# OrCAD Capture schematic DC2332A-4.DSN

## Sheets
1 PAGE5 - LTC3769: size Custom; company: ANALOG DEVICES; note: DEMO BOARD BILL OF MATERIALS; note: MULTIPHASE BOOST CONVERTER EXPANDER
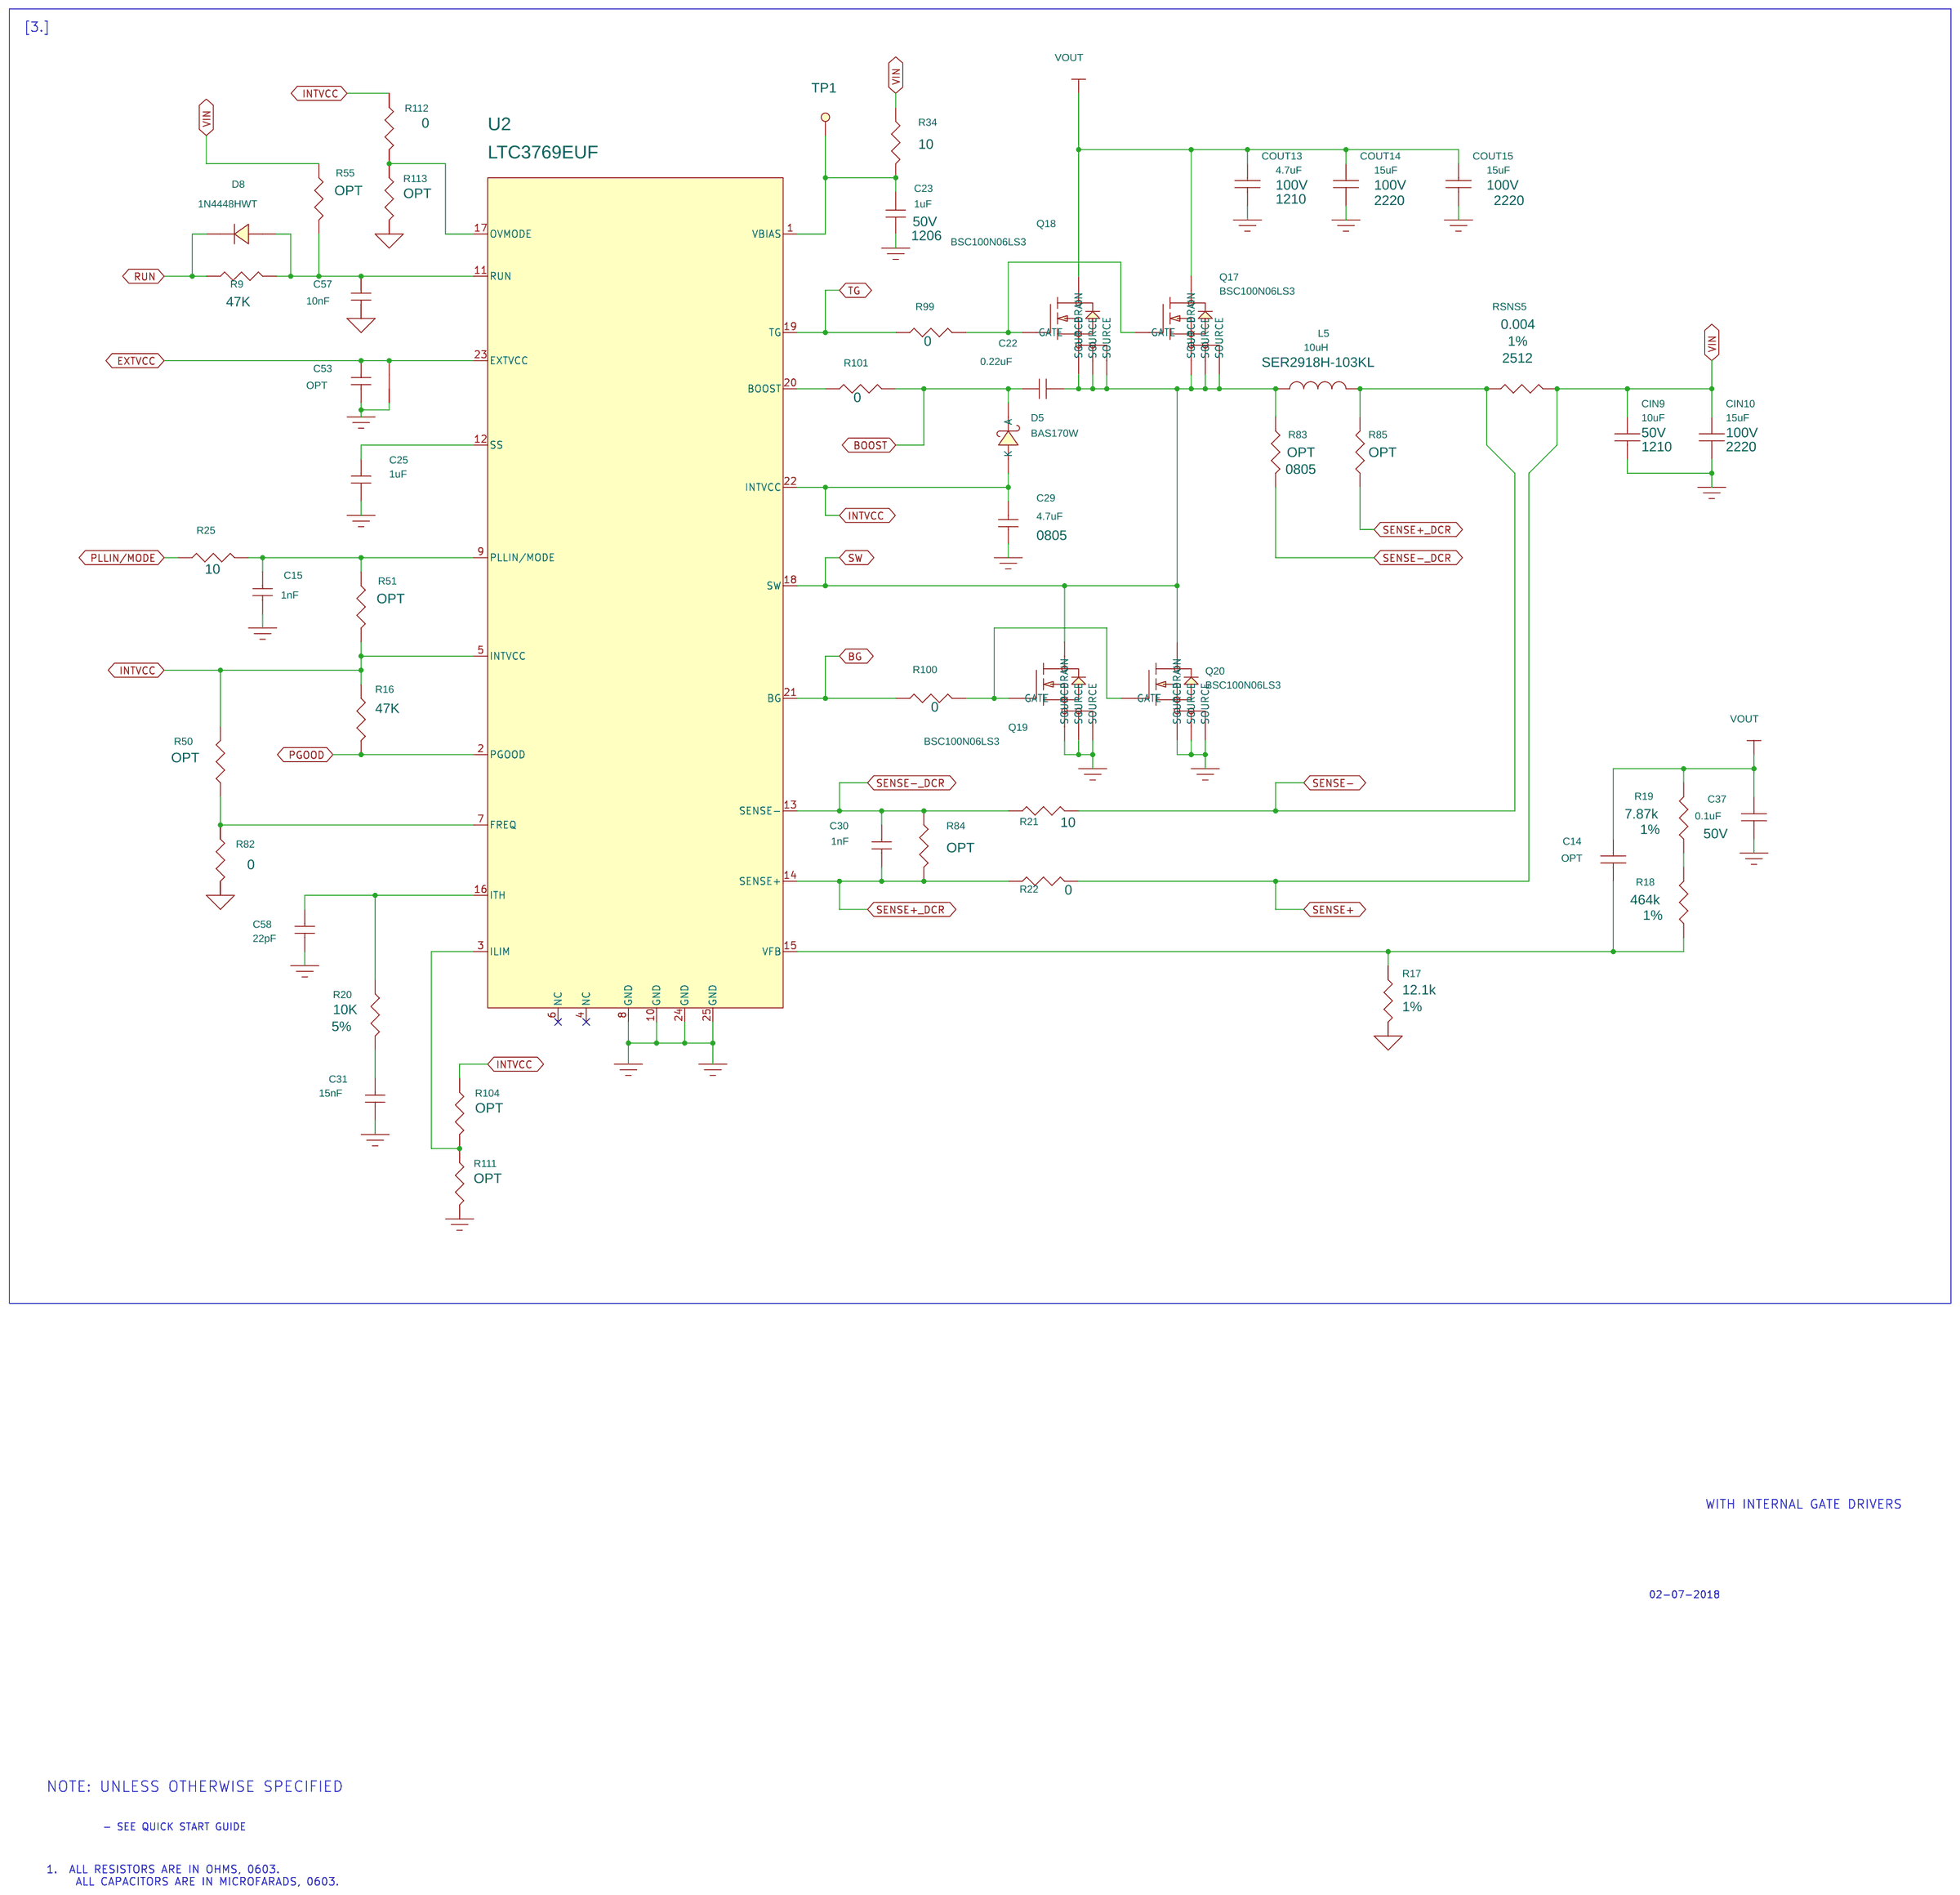
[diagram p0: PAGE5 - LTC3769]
2 PAGE2 - LT8551: size Custom
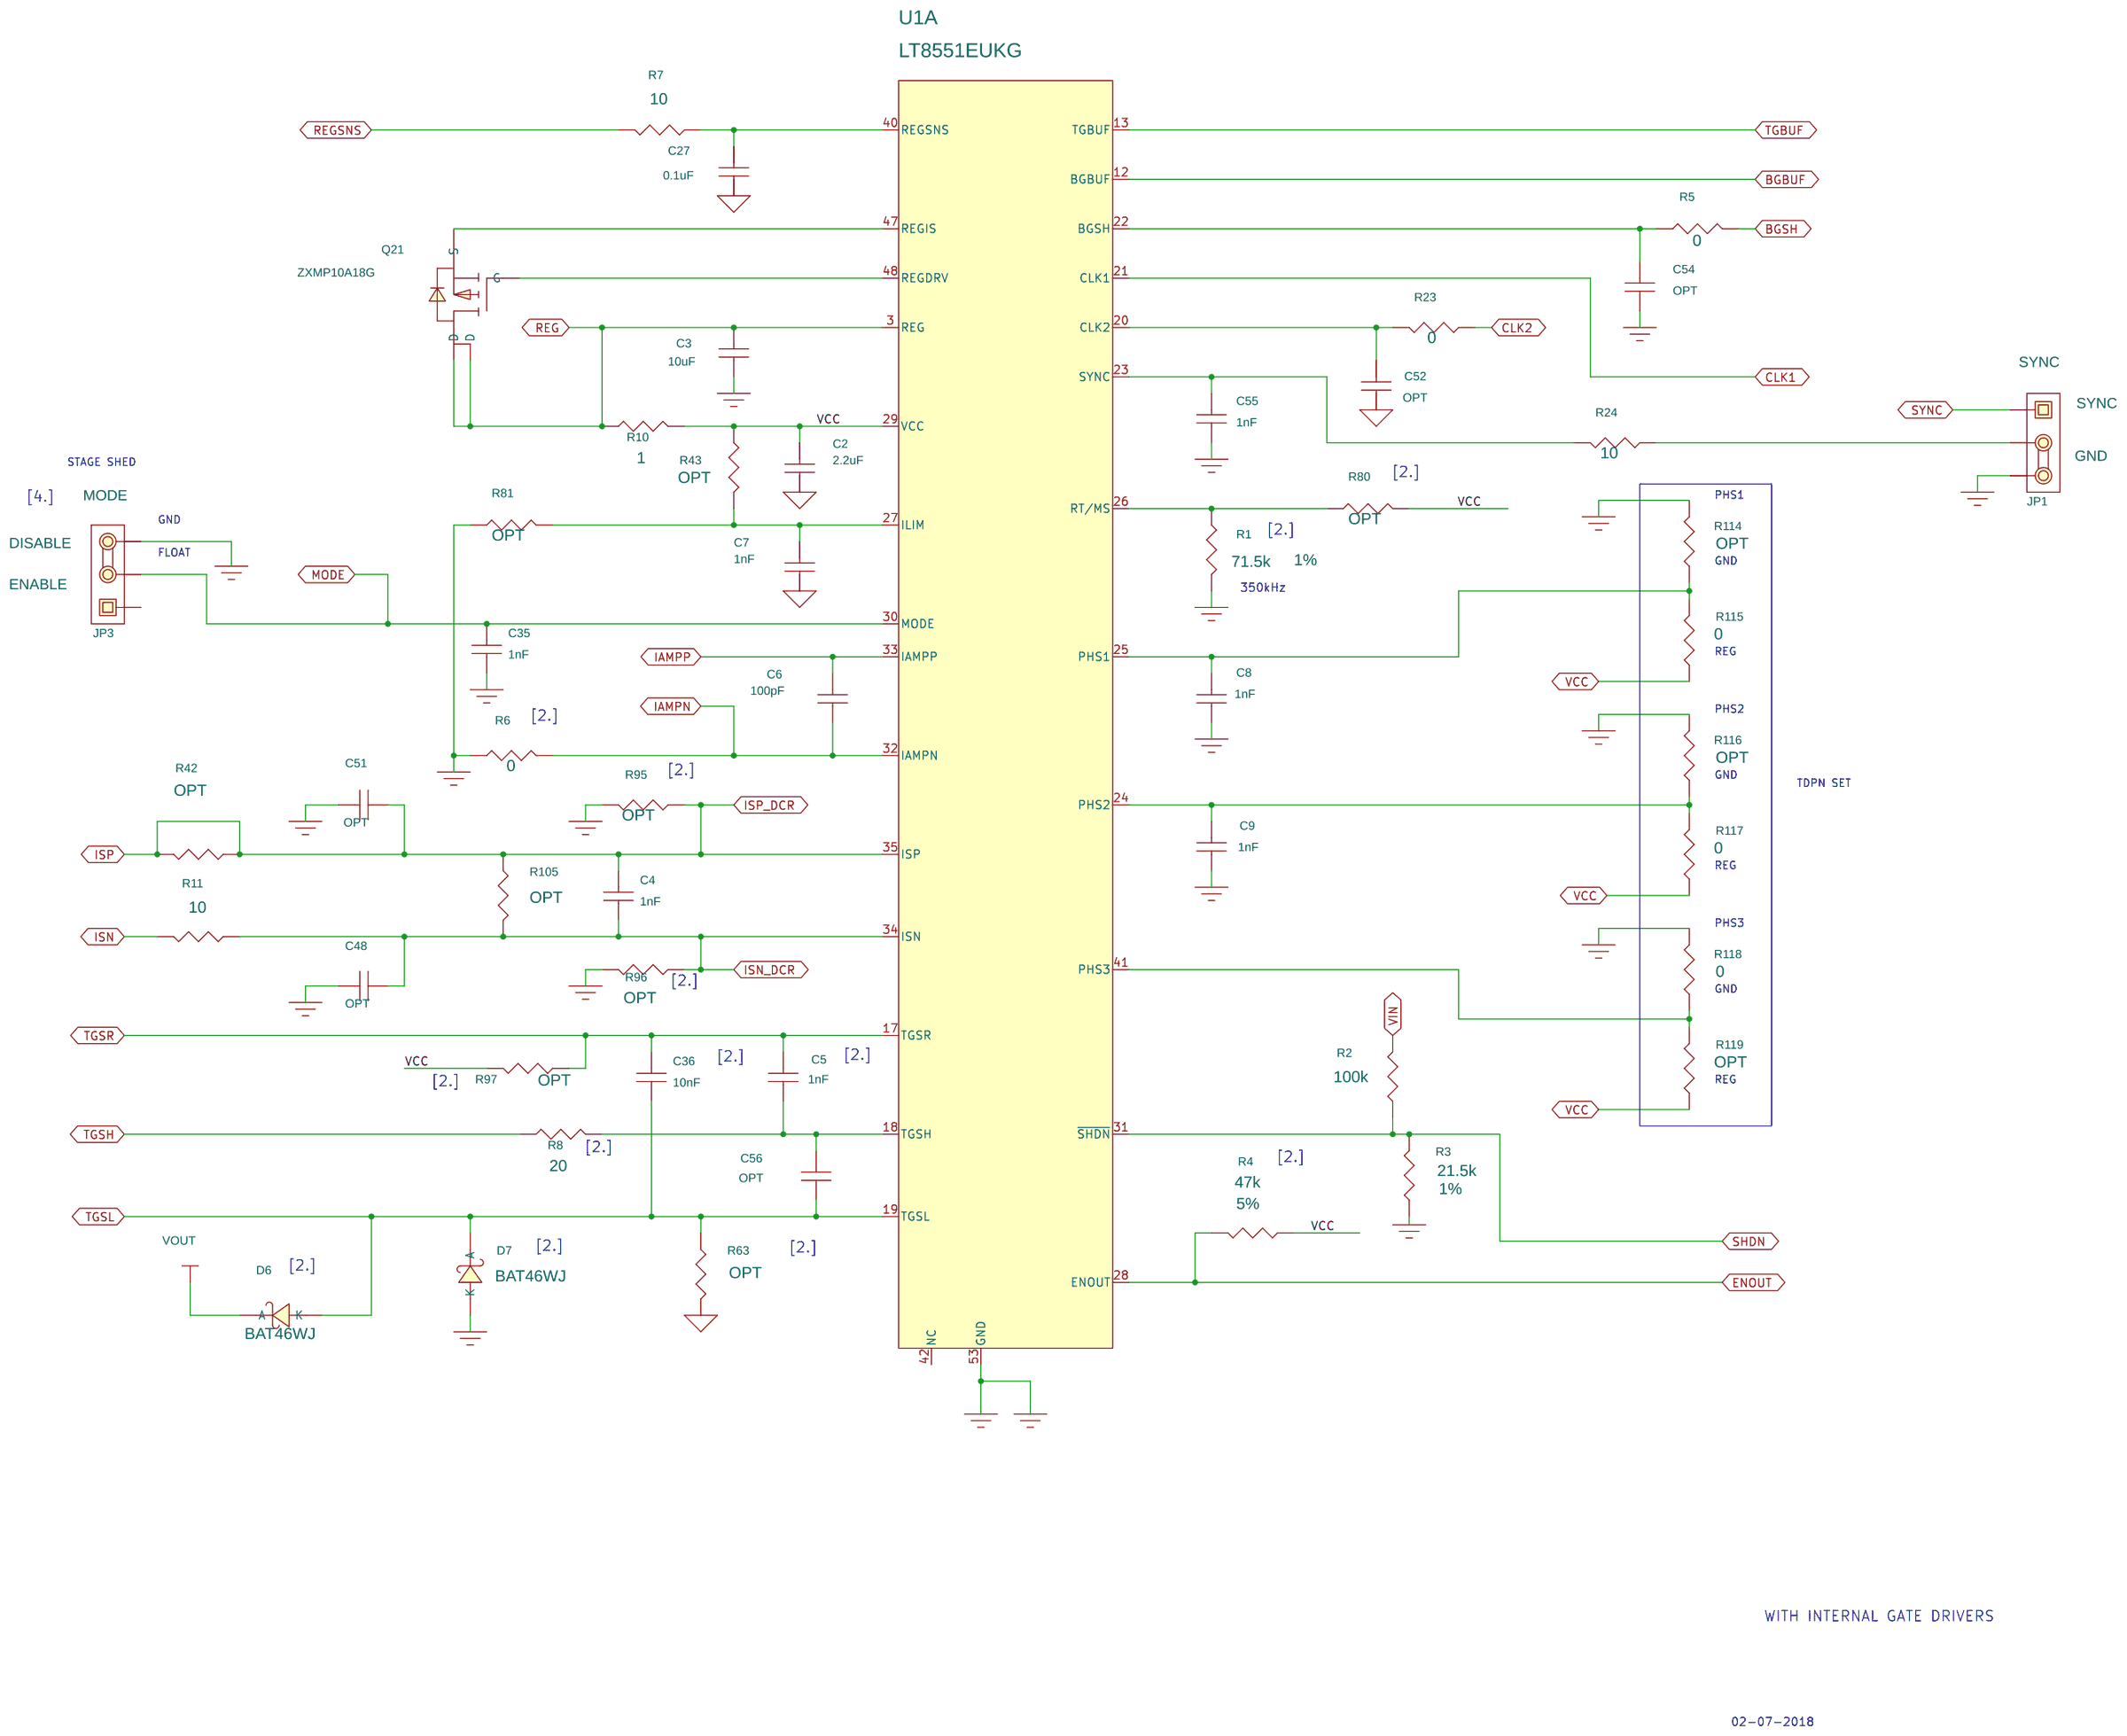
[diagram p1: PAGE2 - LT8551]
3 PAGE4 - LT8551: size Custom
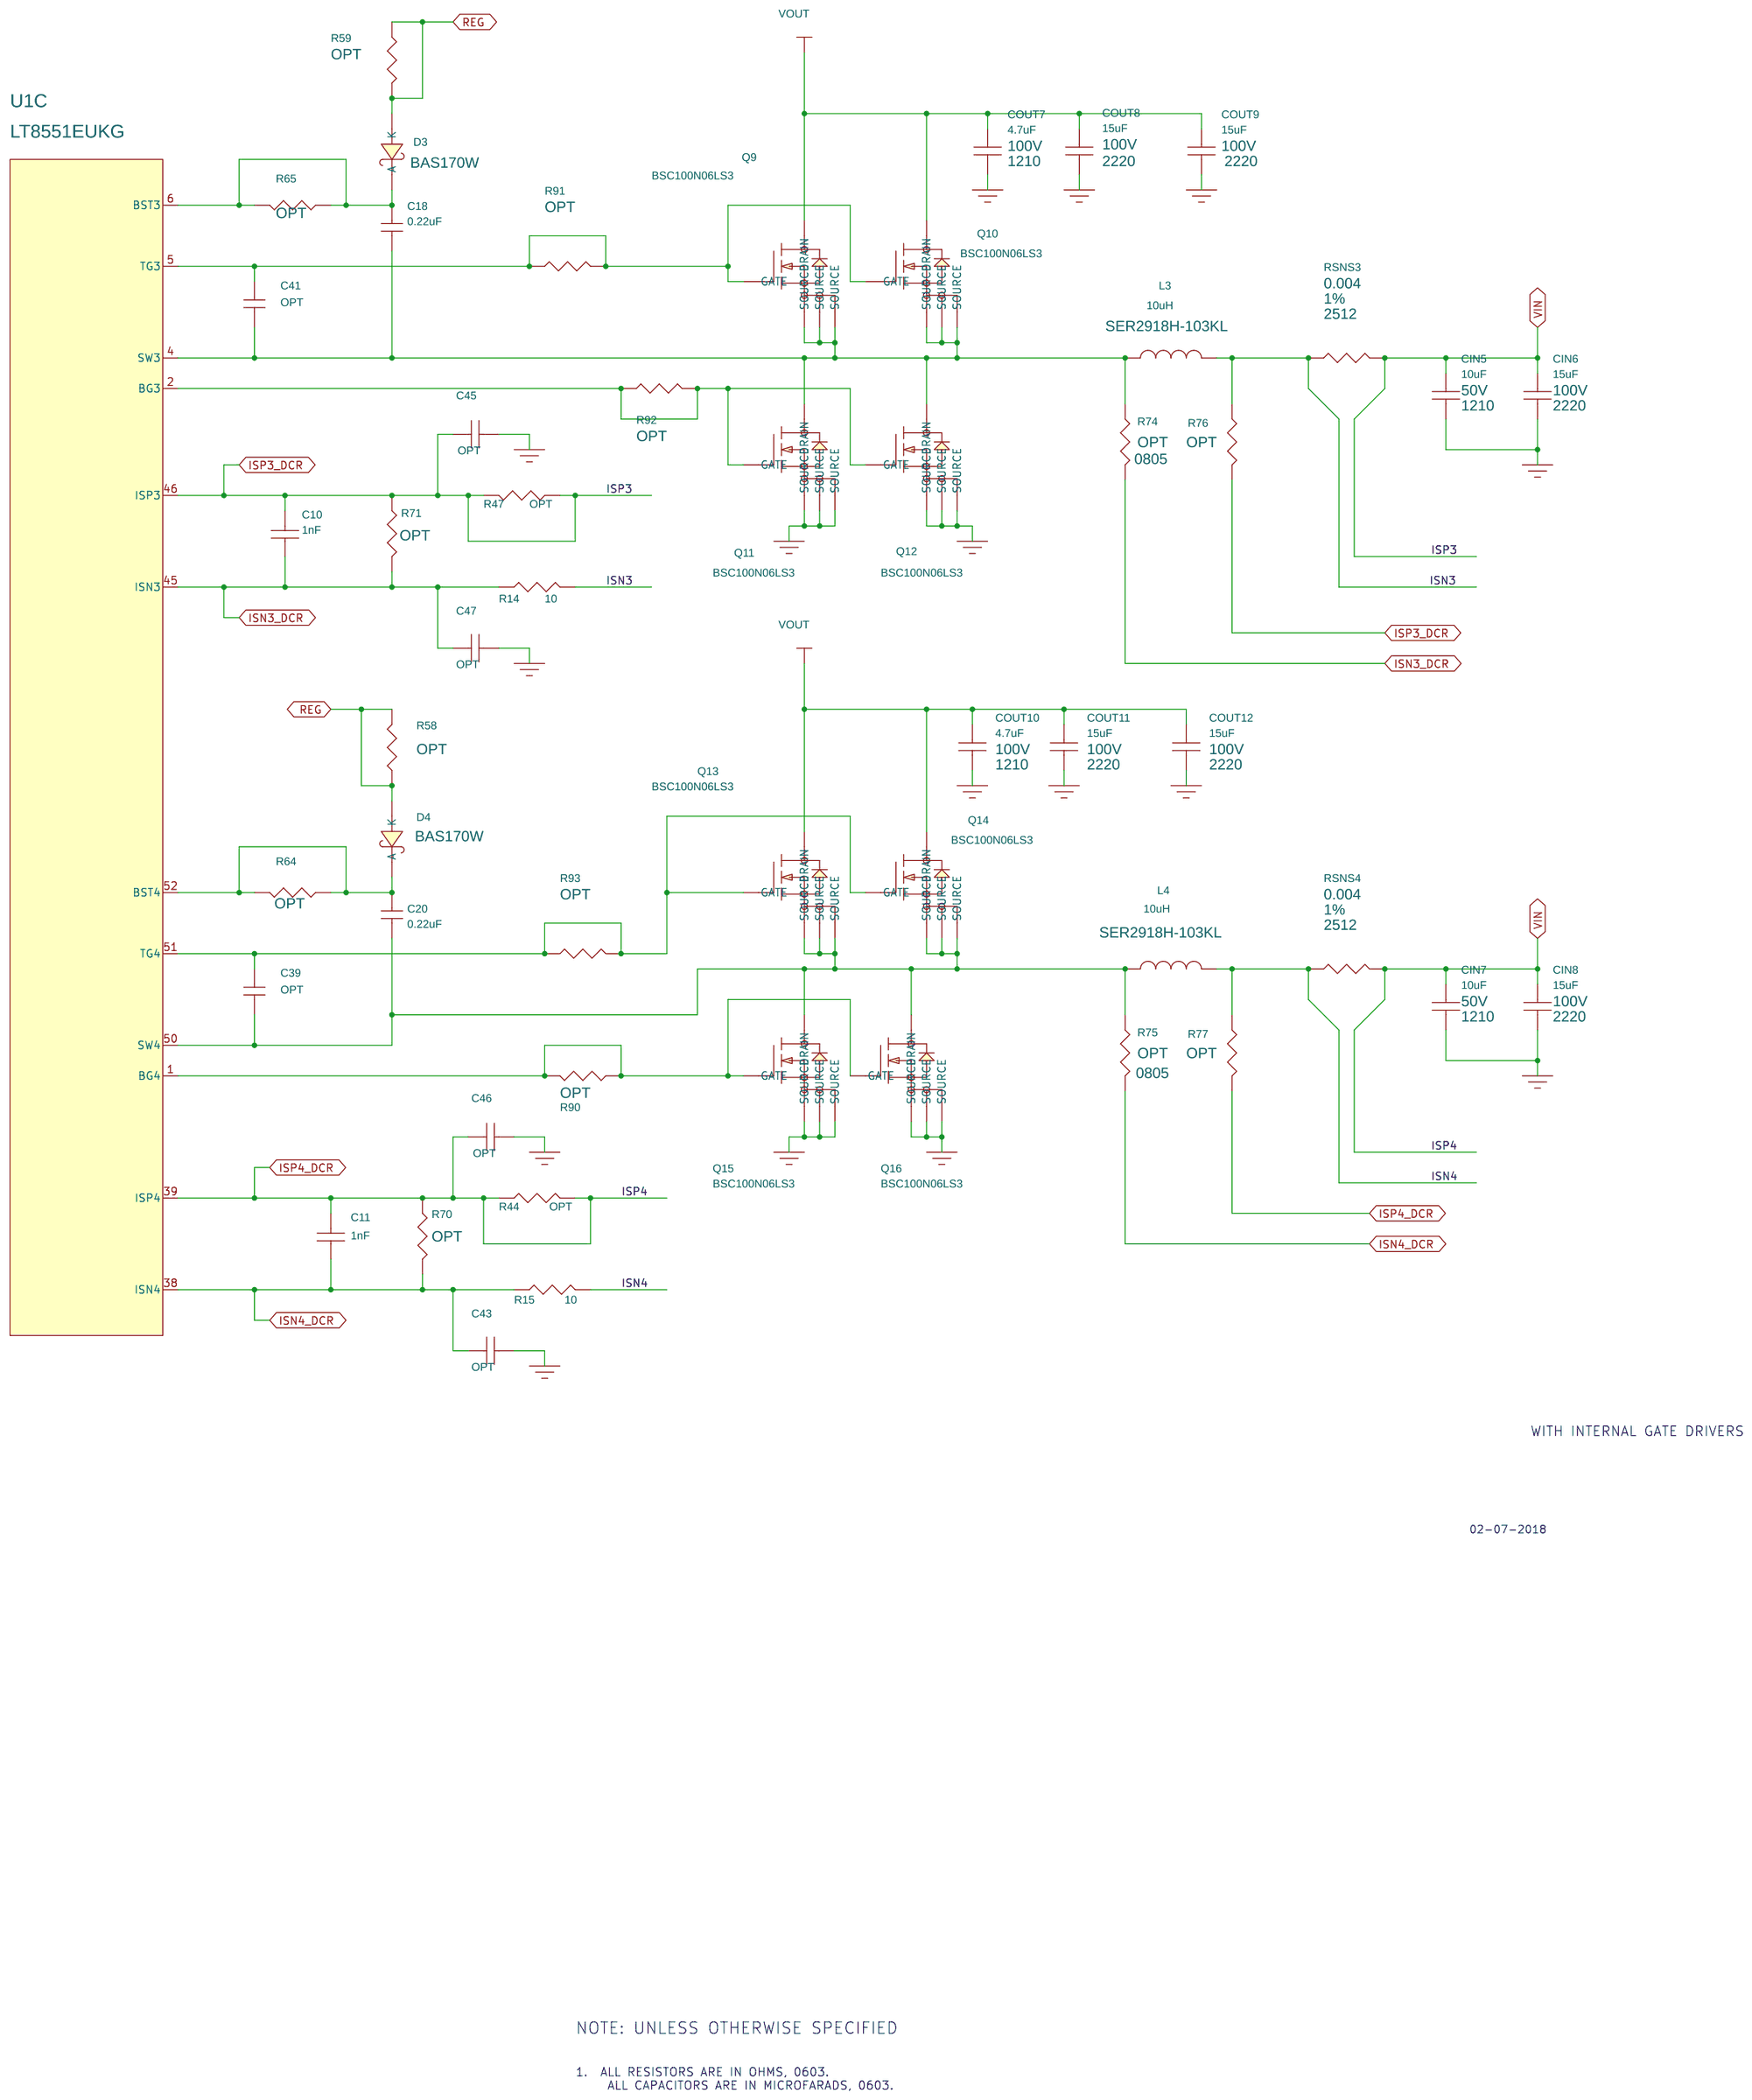
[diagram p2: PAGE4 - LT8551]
4 PAGE3 - LT8551: size Custom
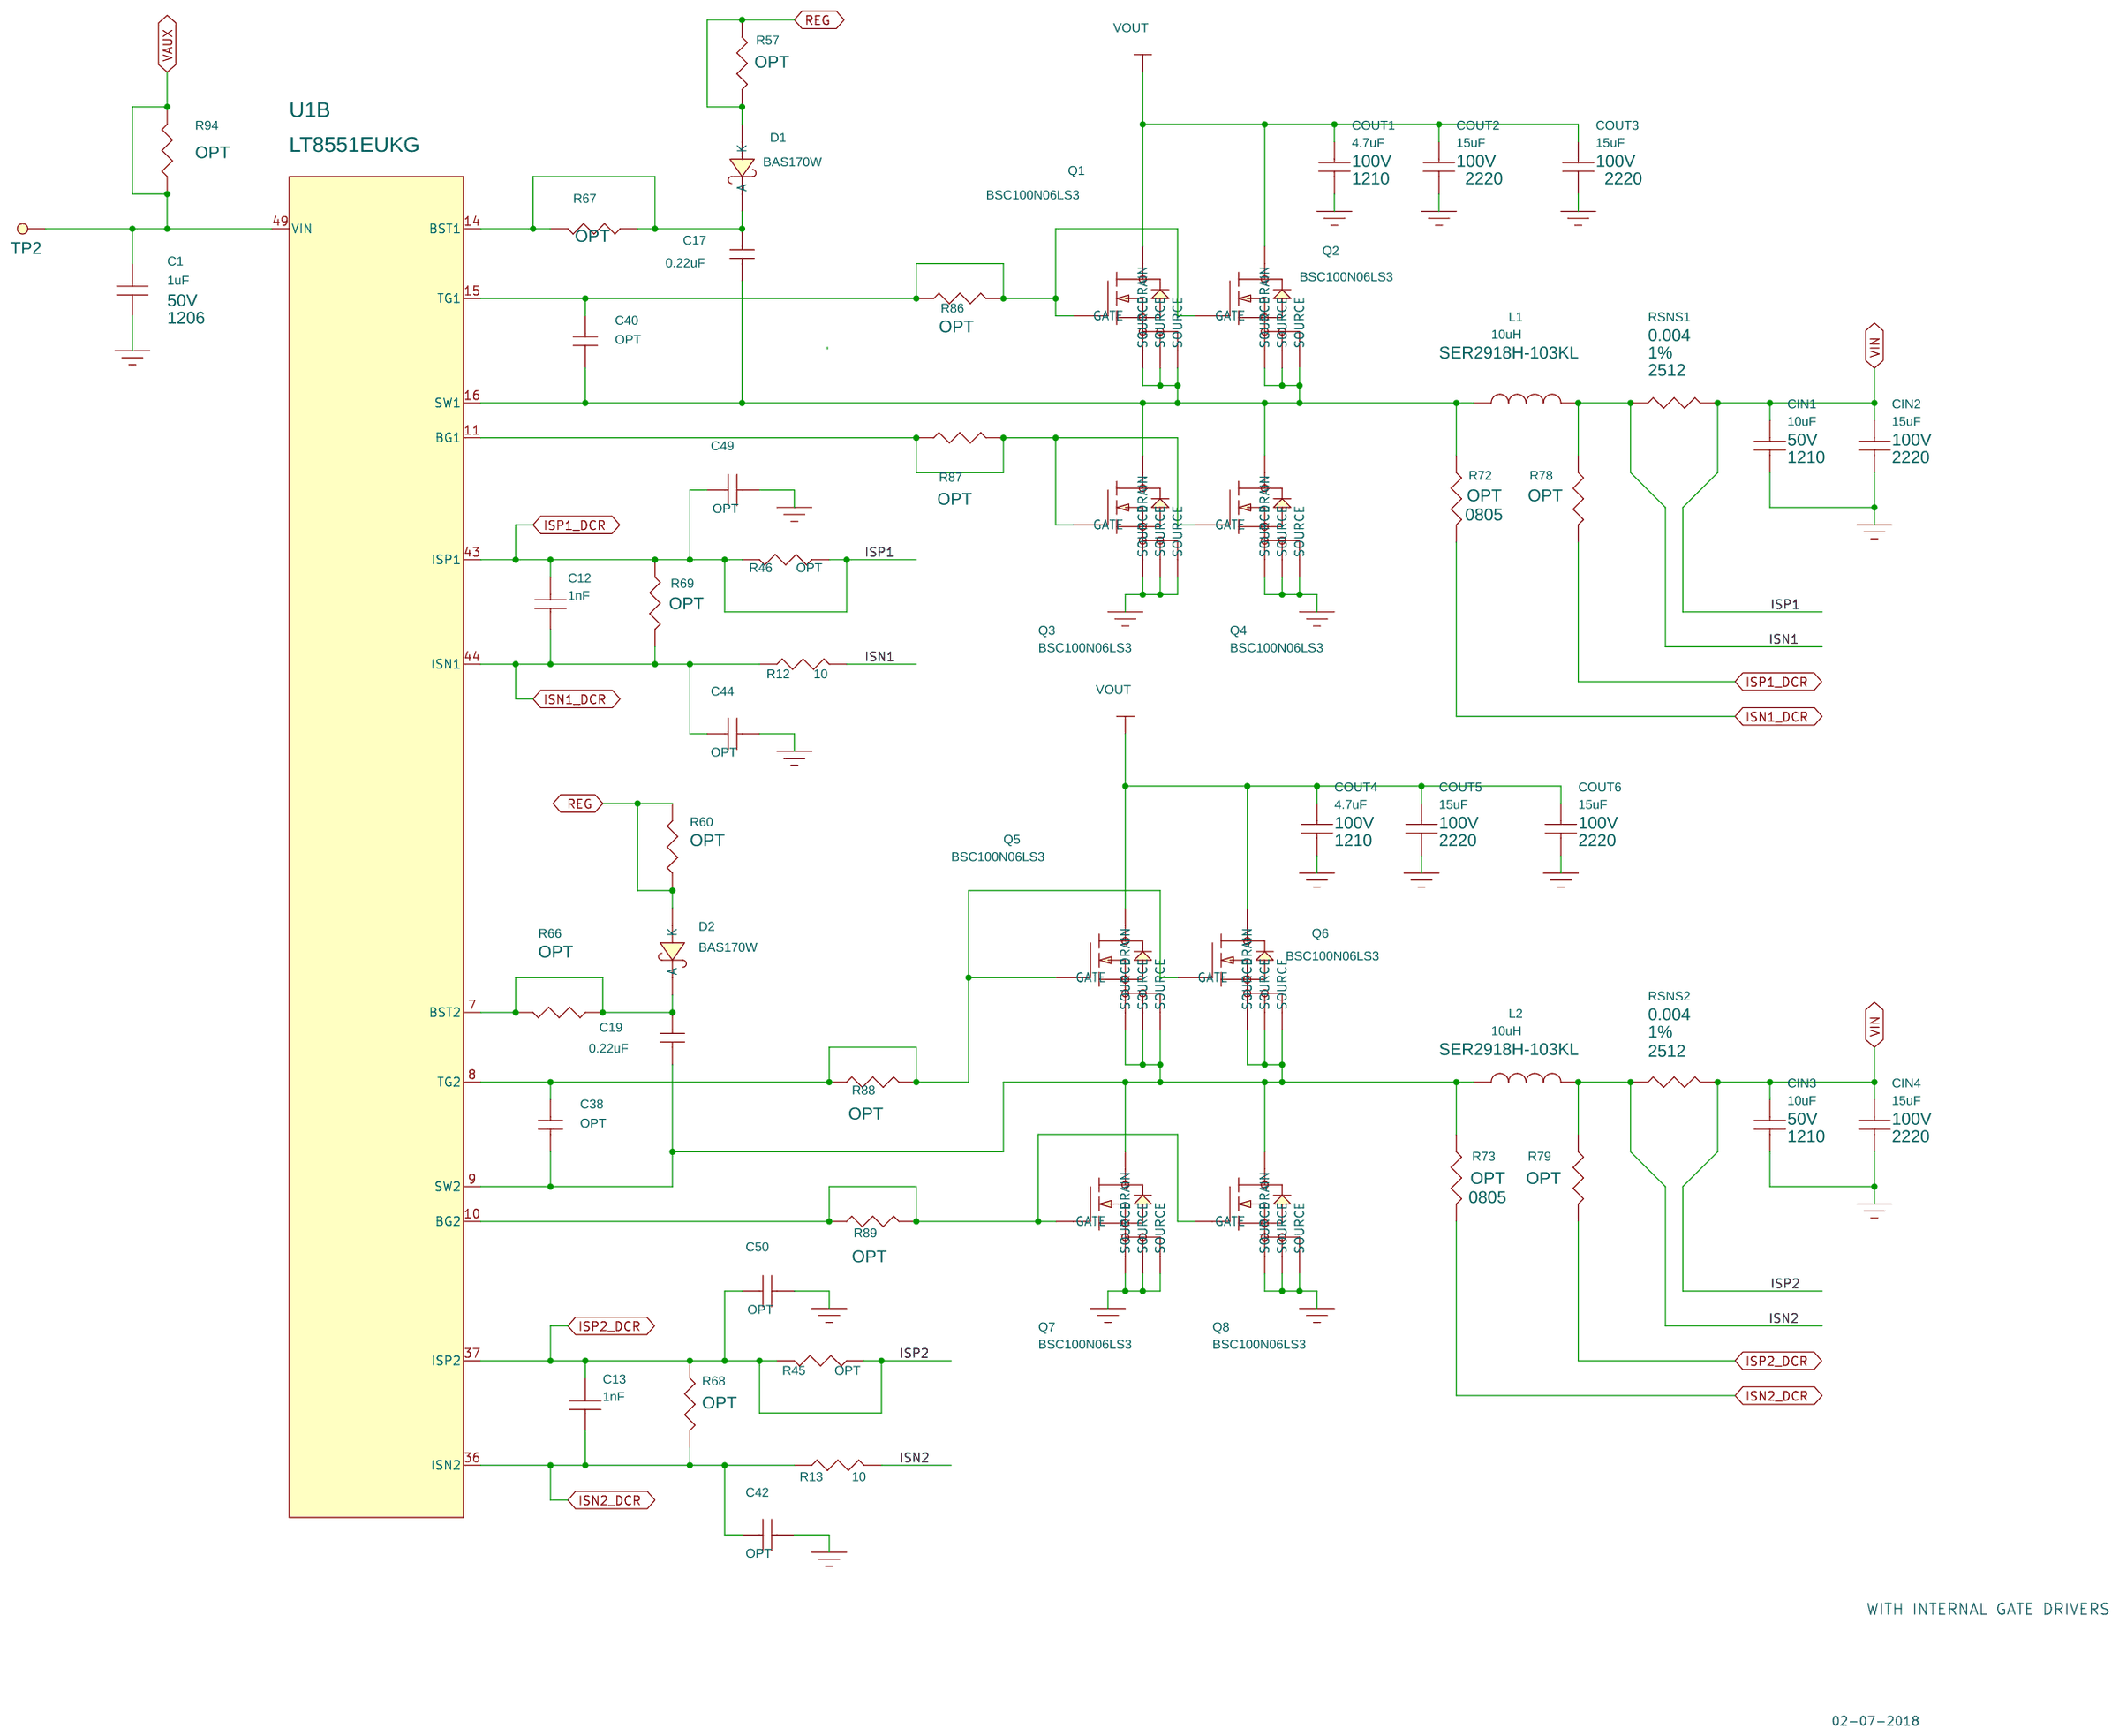
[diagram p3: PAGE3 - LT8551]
5 PAGE1 - TURRETS: size Custom
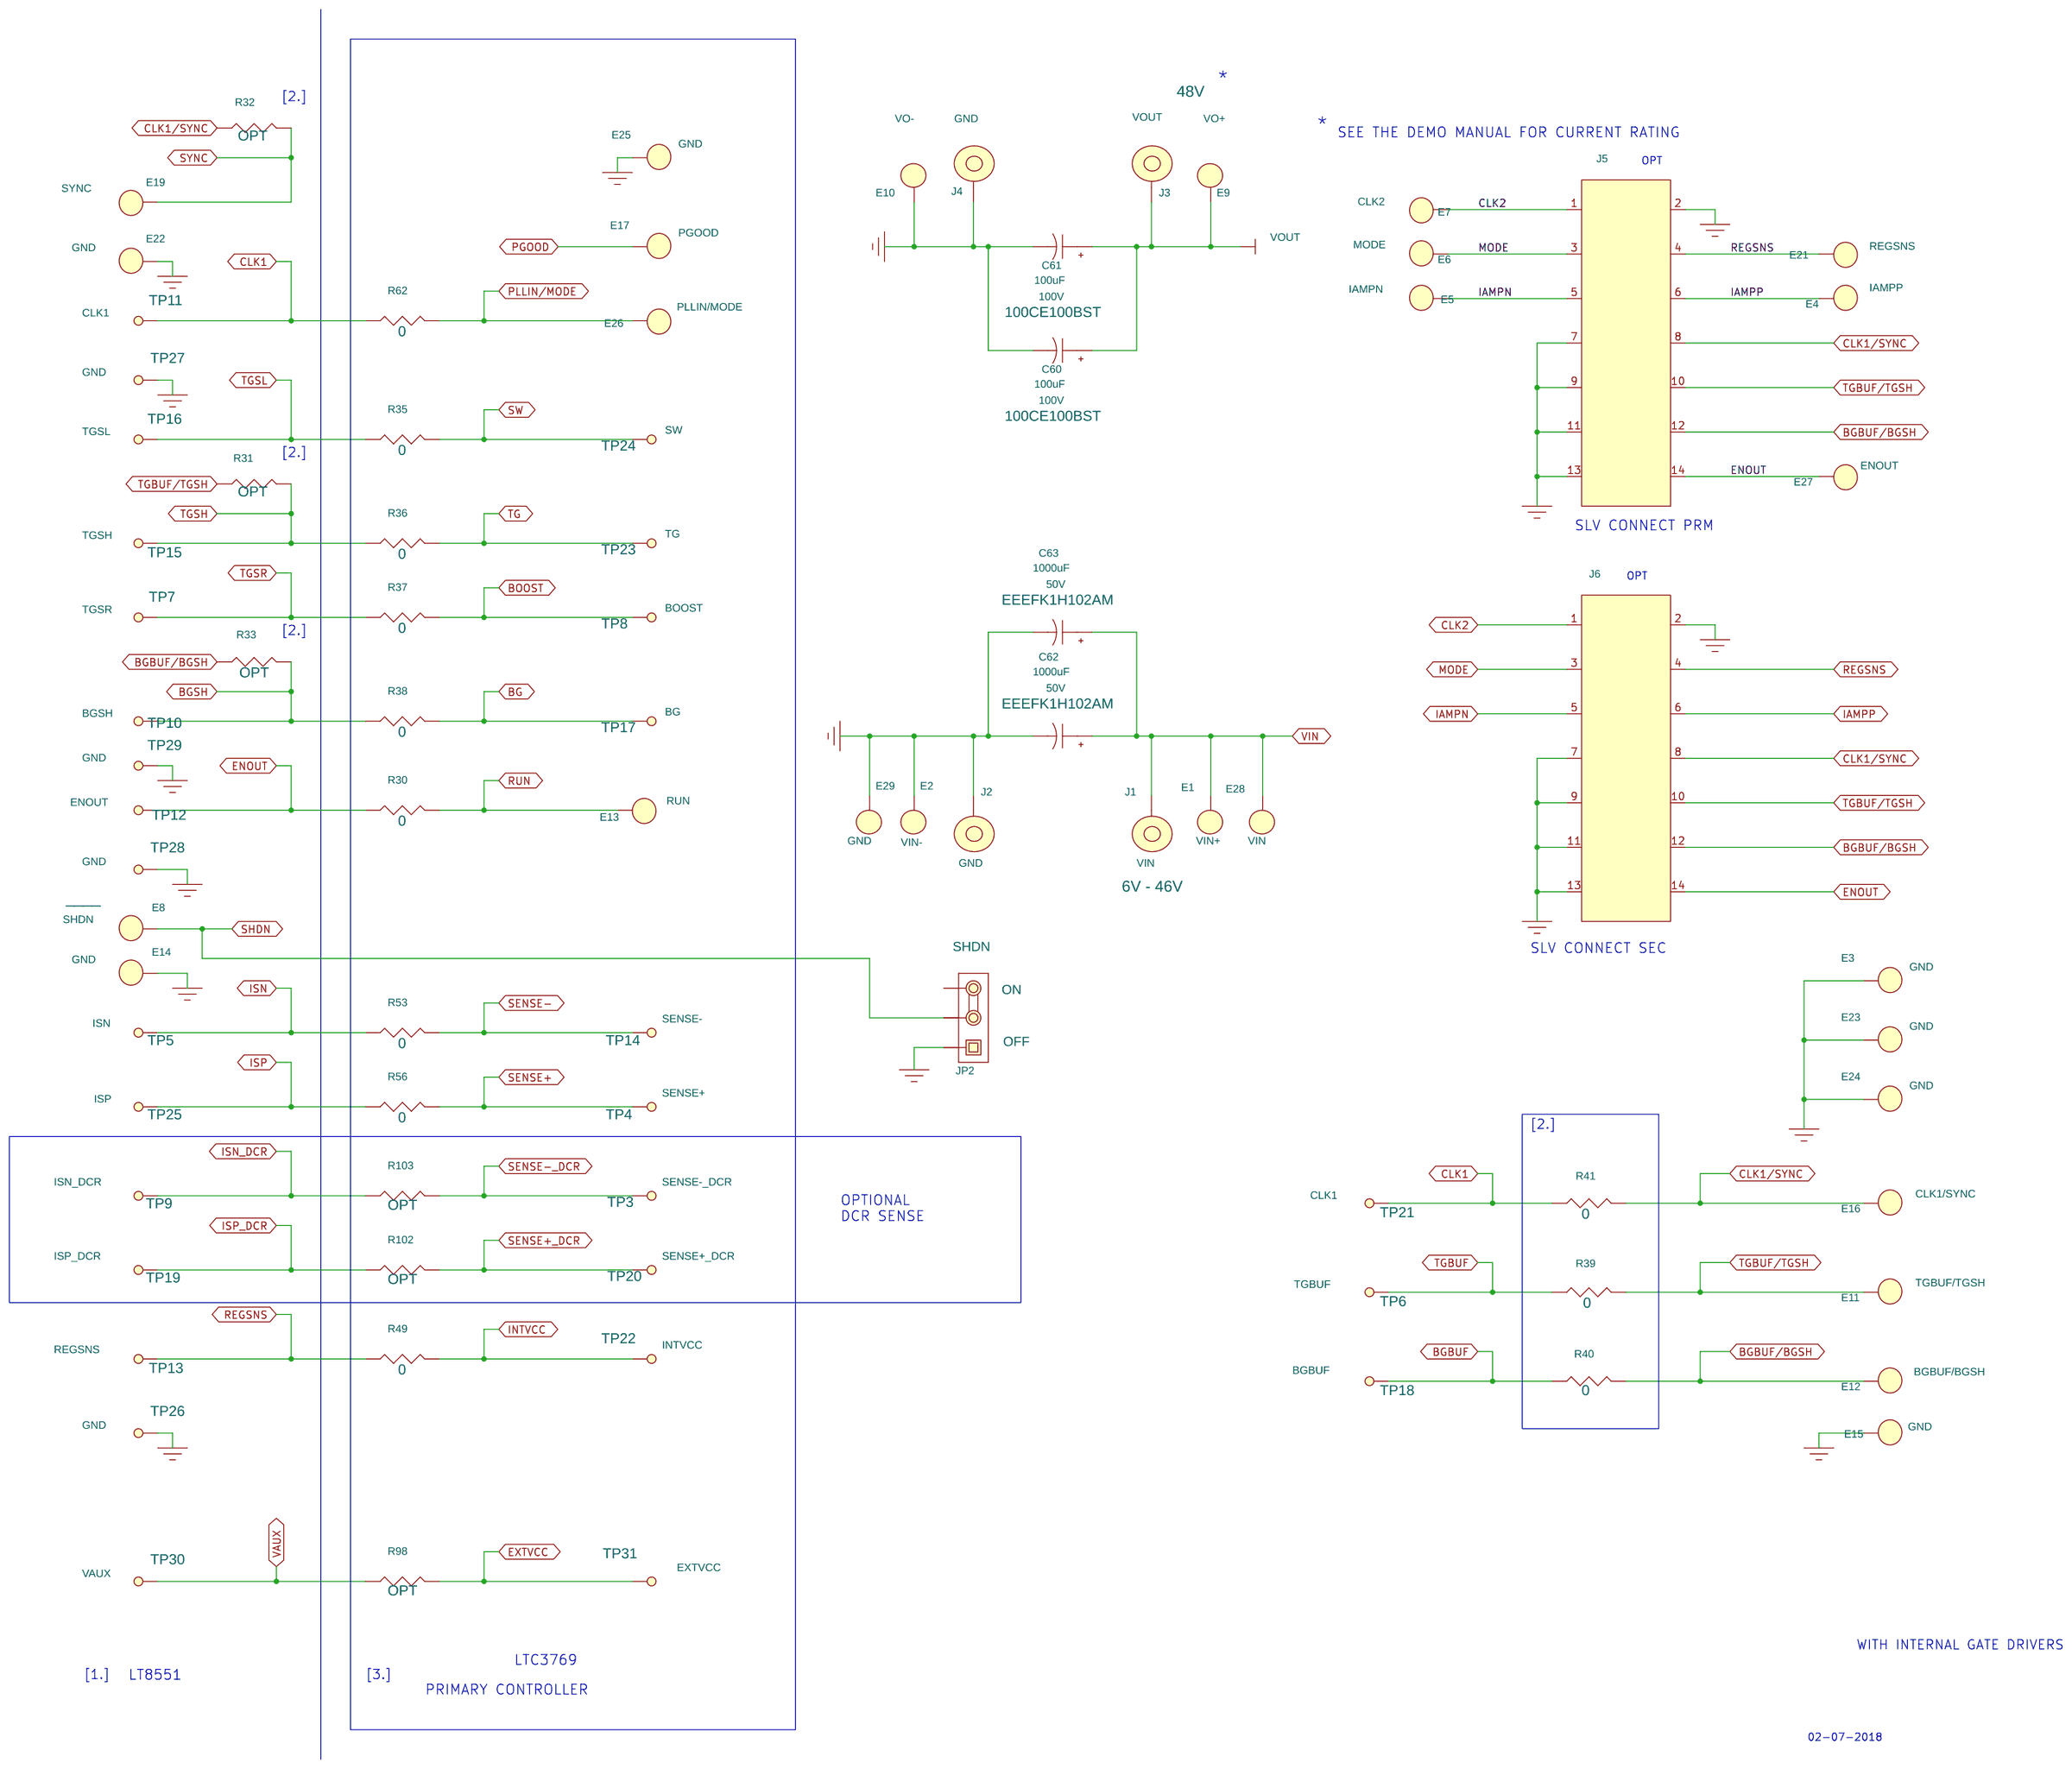
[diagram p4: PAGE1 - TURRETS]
6 PAGE6 - LT8631/NOTES: size Custom
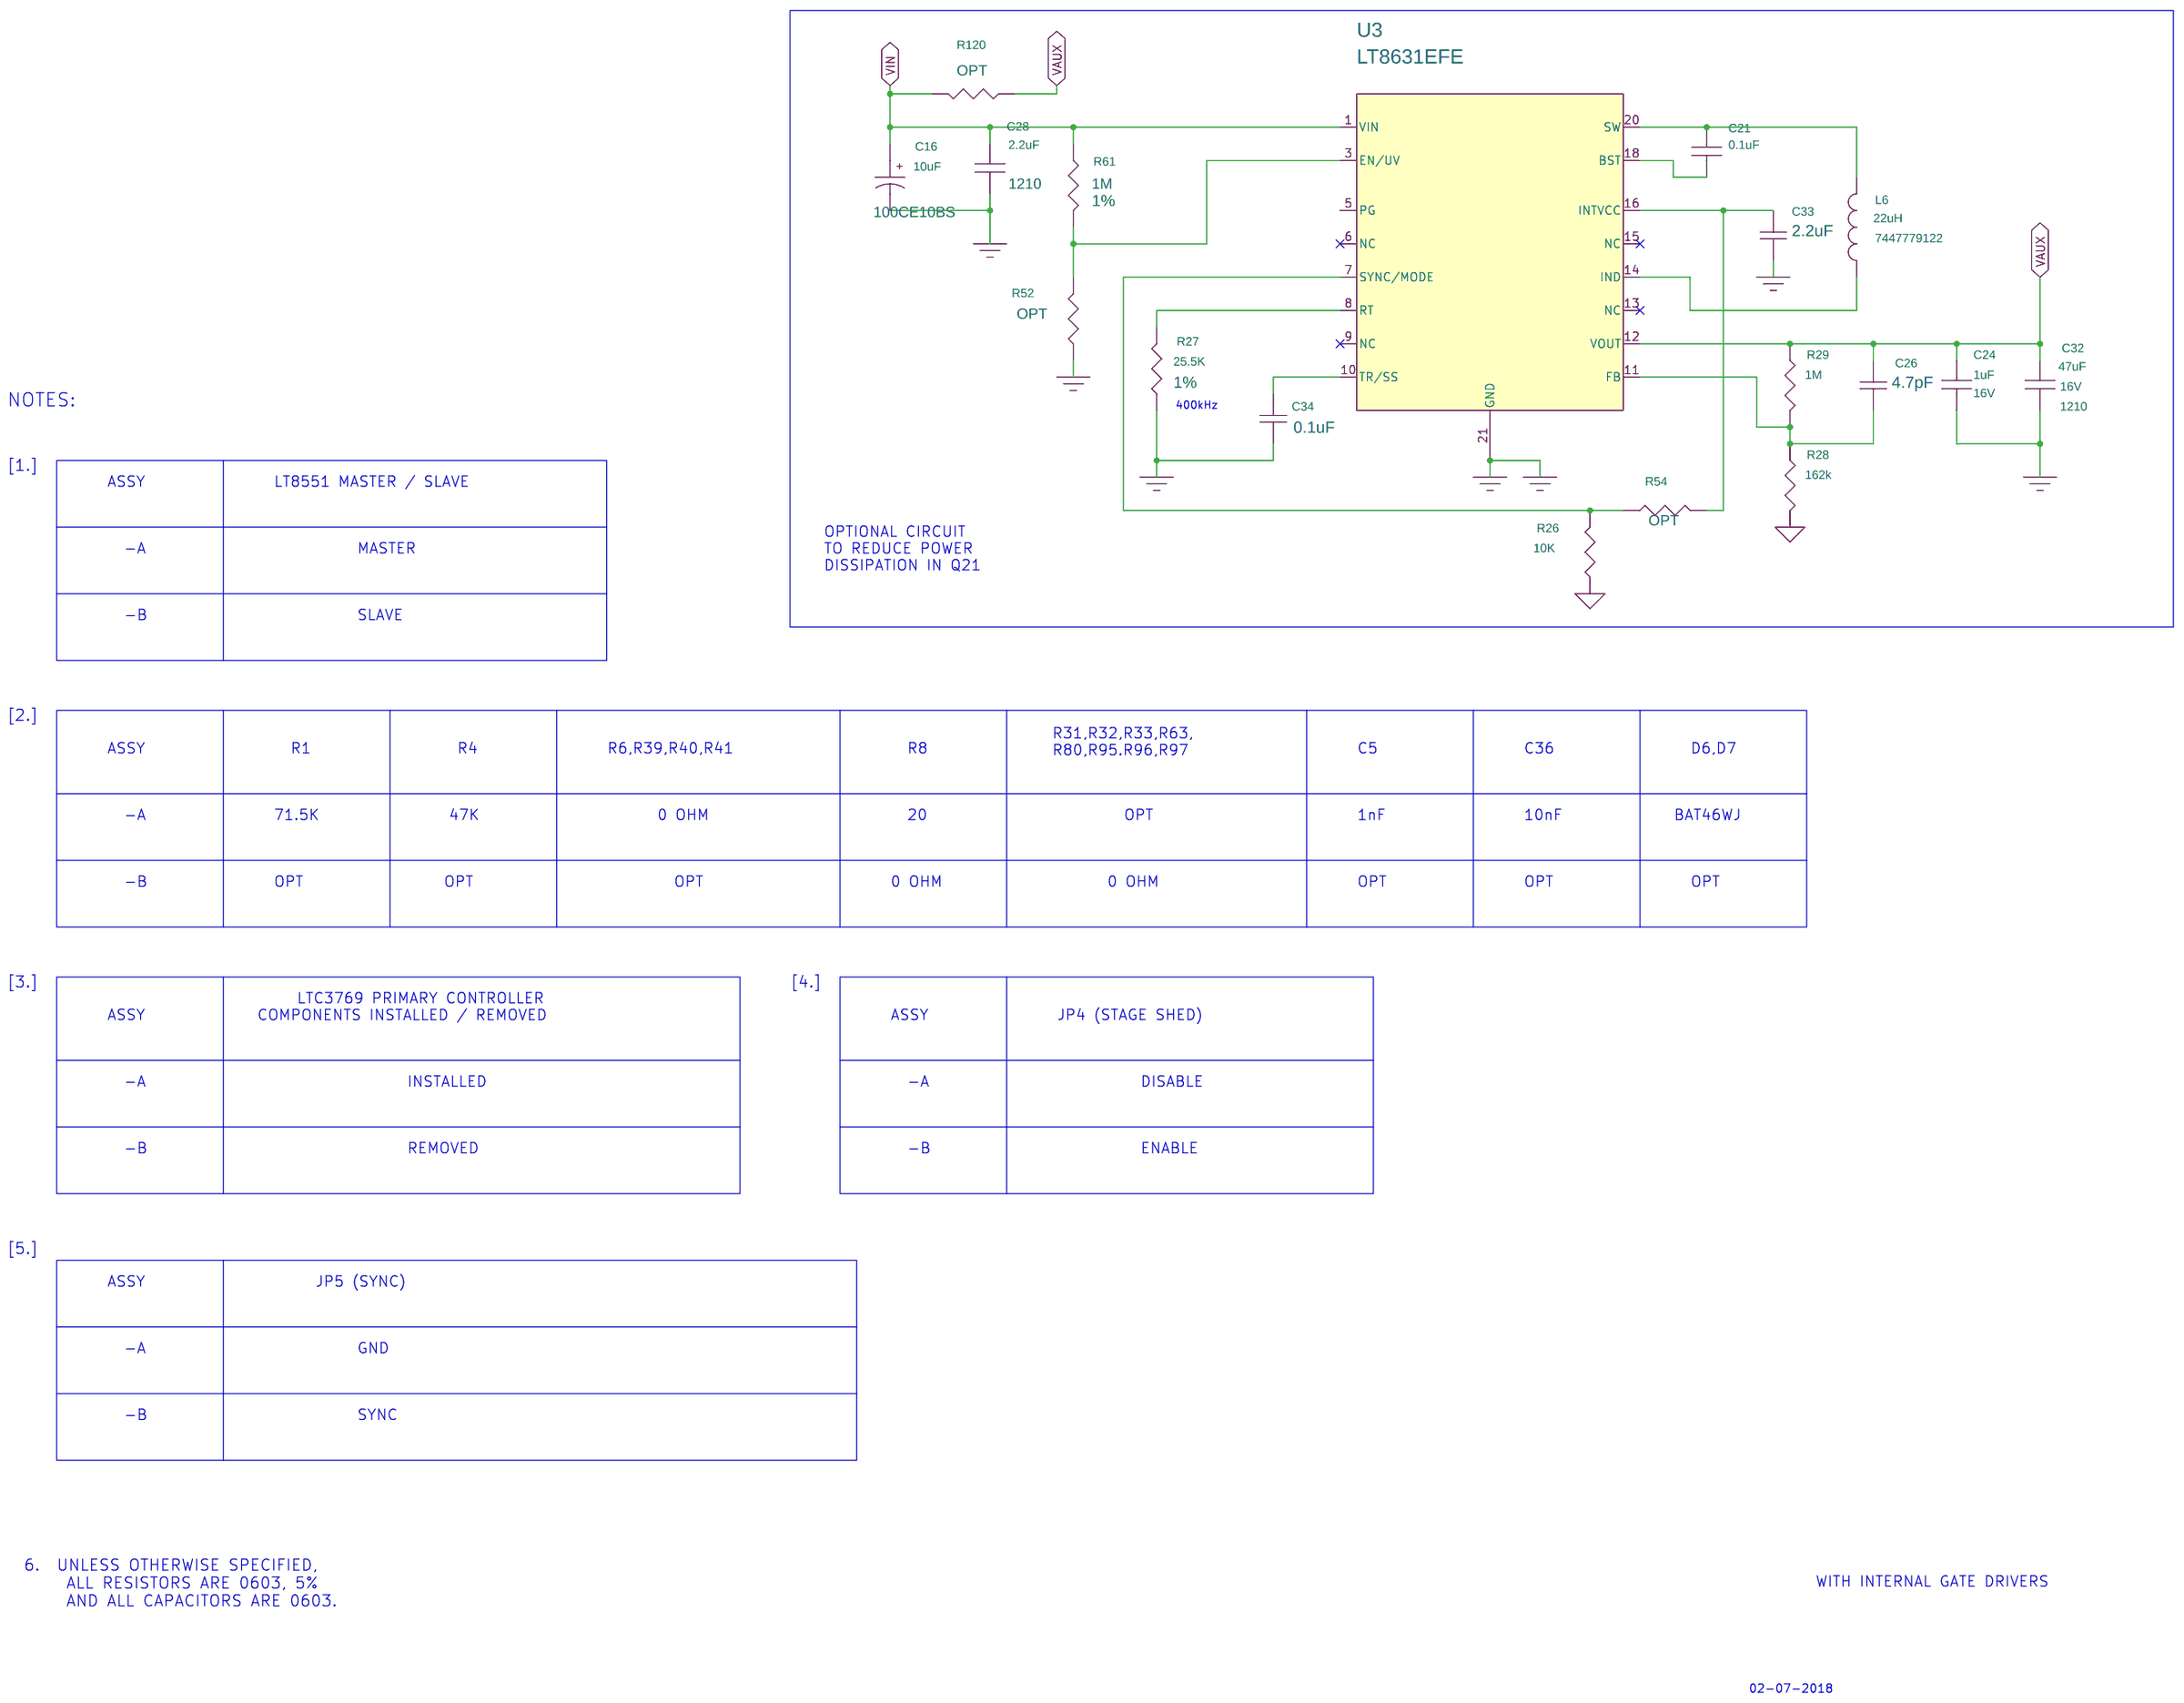
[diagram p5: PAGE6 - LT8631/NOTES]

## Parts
sheet PAGE1 - TURRETS
C60  100uF  [CAP-SMD-16MM]
C61  100uF  [CAP-SMD-16MM]
C62  1000uF  [CAP-PANA-J16]
C63  1000uF  [CAP-PANA-J16]
E1  TURRETS  [MM/2308]
E2  TURRETS  [MM/2308]
E3  TURRETS  [MM/2308]
E4  TURRETS  [MM/2308]
E5  TURRETS  [MM/2308]
E6  TURRETS  [MM/2308]
E7  TURRETS  [MM/2308]
E8  TURRETS  [MM/2308]
E9  TURRETS  [MM/2308]
E10  TURRETS  [MM/2308]
E11  TURRETS  [MM/2308]
E12  TURRETS  [MM/2308]
E13  TURRETS  [MM/2308]
E14  TURRETS  [MM/2308]
E15  TURRETS  [MM/2308]
E16  TURRETS  [MM/2308]
E17  TURRETS  [MM/2308]
E19  TURRETS  [MM/2308]
E21  TURRETS  [MM/2308]
E22  TURRETS  [MM/2308]
E23  TURRETS  [MM/2308]
E24  TURRETS  [MM/2308]
E25  TURRETS  [MM/2308]
E26  TURRETS  [MM/2308]
E27  TURRETS  [MM/2308]
E28  TURRETS  [TURRET_2501]
E29  TURRETS  [TURRET_2501]
J1  Testpoint  [CON\LUG\10]
J2  Testpoint  [CON\LUG\10]
J3  Testpoint  [CON\LUG\10]
J4  Testpoint  [CON\LUG\10]
J5  HD2X7-079-MOLEX  [HD2X7-079-MOLEX]
J6  HD2X7-079-MOLEX  [HD2X7-079-MOLEX]
JP2  3 Pins 2mm Ctrs.  [JP3X1/079]
R30  0  [0603]
R31  OPT  [0603]
R32  OPT  [0603]
R33  OPT  [0603]
R35  0  [0603]
R36  0  [0603]
R37  0  [0603]
R38  0  [0603]
R39  0  [0603]
R40  0  [0603]
R41  0  [0603]
R49  0  [0603]
R53  0  [0603]
R56  0  [0603]
R62  0  [0603]
R98  OPT  [0603]
R102  OPT  [0603]
R103  OPT  [0603]
TP3  TP  [TEST-PIN]
TP4  TP  [TEST-PIN]
TP5  TP  [TEST-PIN]
TP6  TP  [TEST-PIN]
TP7  TP  [TEST-PIN]
TP8  TP  [TEST-PIN]
TP9  TP  [TEST-PIN]
TP10  TP  [TEST-PIN]
TP11  TP  [TEST-PIN]
TP12  TP  [TEST-PIN]
TP13  TP  [TEST-PIN]
TP14  TP  [TEST-PIN]
TP15  TP  [TEST-PIN]
TP16  TP  [TEST-PIN]
TP17  TP  [TEST-PIN]
TP18  TP  [TEST-PIN]
TP19  TP  [TEST-PIN]
TP20  TP  [TEST-PIN]
TP21  TP  [TEST-PIN]
TP22  TP  [TEST-PIN]
TP23  TP  [TEST-PIN]
TP24  TP  [TEST-PIN]
TP25  TP  [TEST-PIN]
TP26  TP  [TEST-PIN]
TP27  TP  [TEST-PIN]
TP28  TP  [TEST-PIN]
TP29  TP  [TEST-PIN]
TP30  TP  [TEST-PIN]
TP31  TP  [TEST-PIN]
XJP6  2mm Ctrs.
sheet PAGE2 - LT8551
C2  2.2uF  [0603]
C3  10uF  [0603]
C4  1nF  [0603]
C5  1nF  [0603]
C6  100pF  [0603]
C7  1nF  [0603]
C8  1nF  [0603]
C9  1nF  [0603]
C27  0.1uF  [0603]
C35  1nF  [0603]
C36  10nF  [0603]
C48  OPT  [0603]
C51  OPT  [0603]
C52  OPT  [0603]
C54  OPT  [0603]
C55  1nF  [0603]
C56  OPT  [0603]
D6  BAT46WJ  [SOD323]
D7  BAT46WJ  [SOD323]
JP1  3 Pins 2mm Ctrs.  [JP3X1/079]
JP3  3 Pins 2mm Ctrs.  [JP3X1/079]
Q21  ZXMP10A18G  [SOT-223]
R1  71.5k  [0603]
R2  100k  [0603]
R3  21.5k  [0603]
R4  47k  [0603]
R5  0  [0603]
R6  0  [0603]
R7  10  [0603]
R8  20  [0603]
R10  1  [0603]
R11  10  [0603]
R23  0  [0603]
R24  10  [0603]
R42  OPT  [0603]
R43  OPT  [0603]
R63  OPT  [0603]
R80  OPT  [0603]
R81  OPT  [0603]
R95  OPT  [0603]
R96  OPT  [0603]
R97  OPT  [0603]
R105  OPT  [0603]
R114  OPT  [0603]
R115  0  [0603]
R116  OPT  [0603]
R117  0  [0603]
R118  0  [0603]
R119  OPT  [0603]
XJP5  2mm Ctrs.
XJP7  2mm Ctrs.
sheet PAGE3 - LT8551
C1  1uF  [1206]
C12  1nF  [0603]
C13  1nF  [0603]
C17  0.22uF  [0603]
C19  0.22uF  [0603]
C38  OPT  [0603]
C40  OPT  [0603]
C42  OPT  [0603]
C44  OPT  [0603]
C49  OPT  [0603]
C50  OPT  [0603]
CIN1  10uF  [1210]
CIN2  15uF  [2220]
CIN3  10uF  [1210]
CIN4  15uF  [2220]
COUT1  4.7uF  [1210]
COUT2  15uF  [2220]
COUT3  15uF  [2220]
COUT4  4.7uF  [1210]
COUT5  15uF  [2220]
COUT6  15uF  [2220]
D1  BAS170W  [SOD323]
D2  BAS170W  [SOD323]
L1  10uH  [IND-SER2900]
L2  10uH  [IND-SER2900]
Q1  BSC100N06LS3  [PG-TDSON-8]
Q2  BSC100N06LS3  [PG-TDSON-8]
Q3  BSC100N06LS3  [PG-TDSON-8]
Q4  BSC100N06LS3  [PG-TDSON-8]
Q5  BSC100N06LS3  [PG-TDSON-8]
Q6  BSC100N06LS3  [PG-TDSON-8]
Q7  BSC100N06LS3  [PG-TDSON-8]
Q8  BSC100N06LS3  [PG-TDSON-8]
R12  10  [0603]
R13  10  [0603]
R45  OPT  [0603]
R46  OPT  [0603]
R57  OPT  [0603]
R60  OPT  [0603]
R66  OPT  [0603]
R67  OPT  [0603]
R68  OPT  [0603]
R69  OPT  [0603]
R72  OPT  [0805]
R73  OPT  [0805]
R78  OPT  [0603]
R79  OPT  [0603]
R86  OPT  [0603]
R87  OPT  [0603]
R88  OPT  [0603]
R89  OPT  [0603]
R94  OPT  [0603]
RSNS1  0.004  [2512]
RSNS2  0.004  [2512]
TP2  VIN-TP  [TEST-PIN]
sheet PAGE4 - LT8551
C10  1nF  [0603]
C11  1nF  [0603]
C18  0.22uF  [0603]
C20  0.22uF  [0603]
C39  OPT  [0603]
C41  OPT  [0603]
C43  OPT  [0603]
C45  OPT  [0603]
C46  OPT  [0603]
C47  OPT  [0603]
CIN5  10uF  [1210]
CIN6  15uF  [2220]
CIN7  10uF  [1210]
CIN8  15uF  [2220]
COUT7  4.7uF  [1210]
COUT8  15uF  [2220]
COUT9  15uF  [2220]
COUT10  4.7uF  [1210]
COUT11  15uF  [2220]
COUT12  15uF  [2220]
D3  BAS170W  [SOD323]
D4  BAS170W  [SOD323]
L3  10uH  [IND-SER2900]
L4  10uH  [IND-SER2900]
Q9  BSC100N06LS3  [PG-TDSON-8]
Q10  BSC100N06LS3  [PG-TDSON-8]
Q11  BSC100N06LS3  [PG-TDSON-8]
Q12  BSC100N06LS3  [PG-TDSON-8]
Q13  BSC100N06LS3  [PG-TDSON-8]
Q14  BSC100N06LS3  [PG-TDSON-8]
Q15  BSC100N06LS3  [PG-TDSON-8]
Q16  BSC100N06LS3  [PG-TDSON-8]
R14  10  [0603]
R15  10  [0603]
R44  OPT  [0603]
R47  OPT  [0603]
R58  OPT  [0603]
R59  OPT  [0603]
R64  OPT  [0603]
R65  OPT  [0603]
R70  OPT  [0603]
R71  OPT  [0603]
R74  OPT  [0805]
R75  OPT  [0805]
R76  OPT  [0603]
R77  OPT  [0603]
R90  OPT  [0603]
R91  OPT  [0603]
R92  OPT  [0603]
R93  OPT  [0603]
RSNS3  0.004  [2512]
RSNS4  0.004  [2512]
U1  LT8551EUKG  [QFN-UKG-7X8-52]  (sections A,B,C)
sheet PAGE5 - LTC3769
C14  OPT  [0603]
C15  1nF  [0603]
C22  0.22uF  [0603]
C23  1uF  [1206]
C25  1uF  [0603]
C29  4.7uF  [0805]
C30  1nF  [0603]
C31  15nF  [0603]
C37  0.1uF  [0603]
C53  OPT  [0603]
C57  10nF  [0603]
C58  22pF  [0603]
CIN9  10uF  [1210]
CIN10  15uF  [2220]
COUT13  4.7uF  [1210]
COUT14  15uF  [2220]
COUT15  15uF  [2220]
D5  BAS170W  [SOD323]
D8  1N4448HWT  [SOD-523]
L5  10uH  [IND-SER2900]
NETTIE  SHORT  [0402S-NOSILK]
Q17  BSC100N06LS3  [PG-TDSON-8]
Q18  BSC100N06LS3  [PG-TDSON-8]
Q19  BSC100N06LS3  [PG-TDSON-8]
Q20  BSC100N06LS3  [PG-TDSON-8]
R9  47K  [0603]
R16  47K  [0603]
R17  12.1k  [0603]
R18  464k  [0603]
R19  7.87k  [0603]
R20  10K  [0603]
R21  10  [0603]
R22  0  [0603]
R25  10  [0603]
R34  10  [0603]
R50  OPT  [0603]
R51  OPT  [0603]
R55  OPT  [0603]
R82  0  [0603]
R83  OPT  [0805]
R84  OPT  [0603]
R85  OPT  [0603]
R99  0  [0603]
R100  0  [0603]
R101  0  [0603]
R104  OPT  [0603]
R111  OPT  [0603]
R112  0  [0603]
R113  OPT  [0603]
RSNS5  0.004  [2512]
TP1  TP3  [TEST-PIN]
U2  LTC3769EUF  [UF-24]
sheet PAGE6 - LT8631/NOTES
C16  10uF  [CAP-CE-BS-6.3X7.7]
C21  0.1uF  [0603]
C24  1uF  [0603]
C26  4.7pF  [0603]
C28  2.2uF  [1210]
C32  47uF  [1210]
C33  2.2uF  [0603]
C34  0.1uF  [0603]
L6  22uH  [IND-7447779]
R26  10K  [0603]
R27  25.5K  [0603]
R28  162k  [0603]
R29  1M  [0603]
R52  OPT  [0603]
R54  OPT  [0603]
R61  1M  [0603]
R120  OPT  [0603]
U3  LT8631EFE  [FE-20L-CB(16)]

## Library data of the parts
C60 C61 = 16TQC47M: 1st Part Field: 100V; 2nd Part Field: 20%; 4th Part Field: SUNCON; 5th Part Field: 100CE100BST; 7th Part Field: CAP.,
C62 C63 = 16TQC47M: 1st Part Field: 50V; 2nd Part Field: 20%; 4th Part Field: PANASONIC; 5th Part Field: EEEFK1H102AM; 7th Part Field: CAP.,
E1 = TURRETS_1: Label: VIN+; Manufacturer P/N: 2308-2; Vendor: Digikey; Vendor P/N: 2308-2
E2 = TURRETS_1: Label: VIN-; Manufacturer P/N: 2308-2; Vendor: Digikey; Vendor P/N: 2308-2
E3 E14 E15 E22-E25 E29 = TURRETS_1: Label: GND; Manufacturer P/N: 2308-2; Vendor: Digikey; Vendor P/N: 2308-2
E4 = TURRETS_1: 1st Part Field: ____; Label: IAMPP; Manufacturer P/N: 2308-2; Vendor: Digikey; Vendor P/N: 2308-2
E5 = TURRETS_1: 1st Part Field: ____; Label: IAMPN; Manufacturer P/N: 2308-2; Vendor: Digikey; Vendor P/N: 2308-2
E6 = TURRETS_1: 1st Part Field: ____; Label: MODE; Manufacturer P/N: 2308-2; Vendor: Digikey; Vendor P/N: 2308-2
E7 = TURRETS_1: 1st Part Field: ____; Label: CLK2; Manufacturer P/N: 2308-2; Vendor: Digikey; Vendor P/N: 2308-2
E8 = TURRETS_1: 1st Part Field: ____; Label: SHDN; Manufacturer P/N: 2308-2; Vendor: Digikey; Vendor P/N: 2308-2
E9 = TURRETS_1: Label: VO+; Manufacturer P/N: 2308-2; Vendor: Digikey; Vendor P/N: 2308-2
E10 = TURRETS_1: Label: VO-; Manufacturer P/N: 2308-2; Vendor: Digikey; Vendor P/N: 2308-2
E11 = TURRETS_1: 1st Part Field: ____; Label: TGBUF/TGSH; Manufacturer P/N: 2308-2; Vendor: Digikey; Vendor P/N: 2308-2
E12 = TURRETS_1: 1st Part Field: ____; Label: BGBUF/BGSH; Manufacturer P/N: 2308-2; Vendor: Digikey; Vendor P/N: 2308-2
E13 = TURRETS_1: 1st Part Field: ____; Label: RUN; Manufacturer P/N: 2308-2; Vendor: Digikey; Vendor P/N: 2308-2
E16 = TURRETS_1: 1st Part Field: ____; Label: CLK1/SYNC; Manufacturer P/N: 2308-2; Vendor: Digikey; Vendor P/N: 2308-2
E17 = TURRETS_1: Label: PGOOD; Manufacturer P/N: 2308-2; TEXT: _____; Vendor: Digikey; Vendor P/N: 2308-2
E19 = TURRETS_1: 1st Part Field: ____; Label: SYNC; Manufacturer P/N: 2308-2; Vendor: Digikey; Vendor P/N: 2308-2
E21 = TURRETS_1: 1st Part Field: ____; Label: REGSNS; Manufacturer P/N: 2308-2; Vendor: Digikey; Vendor P/N: 2308-2
E26 = TURRETS_1: Label: PLLIN/MODE; Manufacturer P/N: 2308-2; Vendor: Digikey; Vendor P/N: 2308-2
E27 = TURRETS_1: 1st Part Field: ____; Label: ENOUT; Manufacturer P/N: 2308-2; Vendor: Digikey; Vendor P/N: 2308-2
E28 = TURRETS_1: Label: VIN; Manufacturer P/N: 2308-2; Vendor: Digikey; Vendor P/N: 2308-2
J1 = MillMax-2501-2_1: 10th Part Field: 6V - 46V; 9th Part Field: VIN
J2 J4 = MillMax-2501-2_1: 9th Part Field: GND
J3 = MillMax-2501-2_1: 10th Part Field: 48V; 9th Part Field: VOUT
J5 J6 = HD2X7-079-MOLEX_0
JP2 = Samtec_TMM-104-02-L-S_0: 10th Part Field: OFF; 11th Part Field: ON; 13tht Part Field: x; 9th Part Field: SHDN
R1-R3 R5-R8 R10 R11 R17-R19 R21-R25 R30-R43 R49-R51 R53 R55-R60 R62-R67 R80-R82 R86-R105 R111-R119 RSNS1-RSNS5 = CJ06-000M: 1st Part Field: 1/10W; 2nd Part Field: 1%; 4th Part Field: MF; 5th Part Field: PN; 7th Part Field: RES.,
TP3 = TESTPIN-1_1: Label: SENSE-_DCR
TP4 = TESTPIN-1_1: Label: SENSE+
TP5 = TESTPIN-1_1: Label: ISN
TP6 = TESTPIN-1_1: Label: TGBUF
TP7 = TESTPIN-1_1: Label: TGSR
TP8 = TESTPIN-1_1: Label: BOOST
TP9 = TESTPIN-1_1: Label: ISN_DCR
TP10 = TESTPIN-1_1: Label: BGSH
TP11 TP21 = TESTPIN-1_1: Label: CLK1
TP12 = TESTPIN-1_1: Label: ENOUT
TP13 = TESTPIN-1_1: Label: REGSNS
TP14 = TESTPIN-1_1: Label: SENSE-
TP15 = TESTPIN-1_1: Label: TGSH
TP16 = TESTPIN-1_1: Label: TGSL
TP17 = TESTPIN-1_1: Label: BG
TP18 = TESTPIN-1_1: Label: BGBUF
TP19 = TESTPIN-1_1: Label: ISP_DCR
TP20 = TESTPIN-1_1: Label: SENSE+_DCR
TP22 = TESTPIN-1_1: Label: INTVCC
TP23 = TESTPIN-1_1: Label: TG
TP24 = TESTPIN-1_1: Label: SW
TP25 = TESTPIN-1_1: Label: ISP
TP26-TP29 = TESTPIN-1_1: Label: GND
TP30 = TESTPIN-1_1: Label: VAUX
TP31 = TESTPIN-1_1: Label: EXTVCC
XJP5-XJP7 = Samtec_2SN-BK-G_1
C2 = 06033A102JAT2A: 1st Part Field: 16V; 2nd Part Field: 10%; 3rd Part Field: X7R; 4th Part Field: MURATA; 5th Part Field: GRM188R61C225KE15D
C3-C13 C27 C35 C36 C42-C52 C54-C56 = 06033A102JAT2A
D6 D7 = CMDSH-3-LTC_0: 4th Part Field: NEXPERIA
JP1 = Samtec_TMM-104-02-L-S_0: 10th Part Field: SYNC; 11th Part Field: GND; 13tht Part Field: x; 9th Part Field: SYNC
JP3 = Samtec_TMM-104-02-L-S_0: 10th Part Field: ENABLE; 11th Part Field: DISABLE; 13tht Part Field: x; 9th Part Field: MODE
Q21 = Si2335DS_0
R4 R9 R16 R20 = CJ06-000M: 1st Part Field: 1/10W; 2nd Part Field: 5%; 4th Part Field: MF; 5th Part Field: PN; 7th Part Field: RES.,
C1 = 06033A102JAT2A: 1st Part Field: 50V; 2nd Part Field: 1%
C15 C17-C20 C22 C25 C30 C31 C38-C41 C53 C57 C58 = 06033C104KAT2A
CIN1 CIN3 CIN5 CIN7 CIN9 = EMK212BJ475MG: 10th Part Field: KRM55WR; 1st Part Field: 50V; 3rd Part Field: X7R
CIN2 CIN4 CIN6 CIN8 CIN10 COUT2 COUT3 COUT5 COUT6 COUT8 COUT9 COUT11 COUT12 COUT14 COUT15 = EMK212BJ475MG: 10th Part Field: KRM55WR; 1st Part Field: 100V; 3rd Part Field: X7R; 4th Part Field: MURATA; 5th Part Field: KRM55WR72A156MH01K
COUT1 COUT4 COUT7 COUT10 COUT13 = EMK212BJ475MG: 1st Part Field: 100V; 3rd Part Field: X7S; 4th Part Field: TDK; 5th Part Field: C3225X7S2A475M200AB
D1-D5 = CMDSH-3-LTC_0: 4th Part Field: INFINEON
L1-L5 = INDUCTOR: MANUFACTURING: SER2918H-103KL
Q1-Q20 = 2N7000_6
R12-R15 R44-R47 = CR16-100JM: 1st Part Field: 1/10W; 2nd Part Field: 1%; 4th Part Field: MF; 5th Part Field: PN; 7th Part Field: RES.,
R26 R52 R54 R61 R68-R79 R83-R85 R120 = RES0603: 1st Part Field: 1/10W; 2nd Part Field: 1%; 4th Part Field: MF; 5th Part Field: PN; 7th Part Field: RES.,
TP1 TP2 = TESTPIN-1_1
U1 = LT8551
C14 C24 = 12061C105MAT2A: 1st Part Field: 16V
C23 = 06033C104KAT2A: 1st Part Field: 50V
C29 = 06033C104KAT2A: 1st Part Field: 6.3V
C37 = 12061C105MAT2A: 1st Part Field: 50V
D8 = 1N4148W
NETTIE = Tie_Point_0402_0
U2 = LT3741FE_17
C16 = 100CE10BS: 4th Part Field: SUNCON
C21 = 0402YD104MAT2A
C26 C34 = CAP0402
C28 = 12061C105MAT2A
C32 = JMK316BJ106KL-T: 1st Part Field: 16V
C33 = CAP0402: 1st Part Field: 16V; 2nd Part Field: 10%; 3rd Part Field: X7R; 4th Part Field: MURATA; 5th Part Field: GRM188R61C225KE15D
L6 = CDRH3D28ENP-6R8NC: 5th Part Field: 7447779122
R27 = RES0402: 1st Part Field: 1/10W; 2nd Part Field: 1%; 4th Part Field: MF; 5th Part Field: PN; 7th Part Field: RES.,
R28 = CRCW040210K0FKED: 1st Part Field: 1/10W; 4th Part Field: MF; 5th Part Field: PN; 7th Part Field: RES.,
R29 = CRCW040231K6FKED: 1st Part Field: 1/10W; 4th Part Field: MF; 5TH PART FIELD: PN; 7th Part Field: RES.,
U3 = LT3982MS_0

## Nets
GND: C1.1 C2.1 C3.1 C7.1 C8.1 C9.1 C15.2 C16.2 C23.1 C24.2 C25.2 C27.1 C28.2 C29.1 C31.2 C32.2 C33.2 C34.2 C35.1 C37.2 C42.2 C43.2 C44.2 C45.2 C46.2 C47.2 C48.2 C49.2 C50.2 C51.2 C52.1 C53.2 C54.1 C55.1 C57.2 C58.2 C60.2 C61.2 C62.2 C63.2 CIN1.2 CIN2.2 CIN3.2 CIN4.2 CIN5.2 CIN6.2 CIN7.2 CIN8.2 CIN9.2 CIN10.2 COUT1.2 COUT2.2 COUT3.2 COUT4.2 COUT5.2 COUT6.2 COUT7.2 COUT8.2 COUT9.2 COUT10.2 COUT11.2 COUT12.2 COUT13.2 COUT14.2 COUT15.2 D7.2(K) E2.1(TP) E3.1(TP) E10.1(TP) E14.1(TP) E15.1(TP) E22.1(TP) E23.1(TP) E24.1(TP) E25.1(TP) E29.1(TP) J2.1 J4.1 J5.2 J5.7 J5.9 J5.11 J5.13 J6.2 J6.7 J6.9 J6.11 J6.13 JP1.3 JP2.1 JP3.3 NETTIE.1 Q3.1(SOURCE) Q3.2(SOURCE) Q3.3(SOURCE) Q4.1(SOURCE) Q4.2(SOURCE) Q4.3(SOURCE) Q7.1(SOURCE) Q7.2(SOURCE) Q7.3(SOURCE) Q8.1(SOURCE) Q8.2(SOURCE) Q8.3(SOURCE) Q11.1(SOURCE) Q11.2(SOURCE) Q11.3(SOURCE) Q12.1(SOURCE) Q12.2(SOURCE) Q12.3(SOURCE) Q15.1(SOURCE) Q15.2(SOURCE) Q15.3(SOURCE) Q16.1(SOURCE) Q16.2(SOURCE) Q16.3(SOURCE) Q19.1(SOURCE) Q19.2(SOURCE) Q19.3(SOURCE) Q20.1(SOURCE) Q20.2(SOURCE) Q20.3(SOURCE) R1.1 R3.1 R6.2 R17.1 R26.2 R27.1 R28.2 R52.2 R63.1 R81.2 R82.1 R95.1 R96.2 R111.1 R113.1 R114.2 R116.2 R118.2 TP26.1 TP27.1 TP28.1 TP29.1 U1.53(GND) U2.8(GND) U2.10(GND) U2.24(GND) U2.25(GND) U3.21(GND)
VCC: C2.2 R4.2 R10.1 R43.1 R80.2 R97.2 R115.1 R117.1 R119.1 U1.29(VCC)
BG: R38.2 R100.2 TP17.1 U2.21(BG)
BGBUF: R40.1 TP18.1 U1.12(BGBUF)
BGBUF/BGSH: E12.1(TP) J5.12 J6.12 R33.1 R40.2
BGSH: R5.2 R33.2 R38.1 TP10.1
BOOST: C22.1 D5.1(A) R37.2 R101.1 TP8.1
CLK1: R41.1 R62.1 TP11.1 TP21.1 U1.21(CLK1)
CLK1/SYNC: E16.1(TP) J5.8 J6.8 R32.1 R41.2
CLK2: E7.1(TP) J5.1 J6.1 R23.1
ENOUT: E27.1(TP) J5.14 J6.14 R4.1 R30.1 TP12.1 U1.28(ENOUT)
EXTVCC: C53.1 NETTIE.2 R98.2 TP31.1 U2.23(EXTVCC)
IAMPN: C6.1 E5.1(TP) J5.5 J6.5 R6.1 U1.32(IAMPN)
IAMPP: C6.2 E4.1(TP) J5.6 J6.6 U1.33(IAMPP)
INTVCC: C29.2 D5.2(K) R16.2 R49.2 R50.2 R51.1 R104.2 R112.2 TP22.1 U2.5(INTVCC) U2.22(INTVCC)
ISN: R11.1 R53.1 TP5.1
ISN1: L1.2 R12.2 R78.1 RSNS1.2
ISN1_DCR: C12.1 C44.1 R12.1 R69.2 R72.2 U1.44(ISN1)
ISN2: L2.2 R13.2 R79.1 RSNS2.2
ISN2_DCR: C13.1 C42.1 R13.1 R68.2 R73.2 U1.36(ISN2)
ISN3: L3.1 R14.2 R76.1 RSNS3.2
ISN3_DCR: C10.1 C47.1 R14.1 R71.2 R74.2 U1.45(ISN3)
ISN4: L4.1 R15.2 R77.1 RSNS4.2
ISN4_DCR: C11.1 C43.1 R15.1 R70.2 R75.2 U1.38(ISN4)
ISN_DCR: C4.1 C48.1 R11.2 R96.1 R103.1 R105.1 TP9.1 U1.34(ISN)
ISP1_DCR: C10.2 C11.2 C12.2 C13.2 C16.1 C28.1 C45.1 C46.1 C49.1 C50.1 C62.1 C63.1 CIN1.1 CIN2.1 CIN3.1 CIN4.1 CIN5.1 CIN6.1 CIN7.1 CIN8.1 CIN9.1 CIN10.1 E1.1(TP) E28.1(TP) J1.1 R2.1 R22.1 R34.2 R44.1 R44.2 R45.1 R45.2 R46.1 R46.2 R47.1 R47.2 R55.2 R56.2 R61.1 R68.1 R69.1 R70.1 R71.1 R76.2 R77.2 R78.2 R79.2 R120.1 RSNS1.1 RSNS2.1 RSNS3.1 RSNS4.1 RSNS5.1 TP4.1 U1.37(ISP2) U1.39(ISP4) U1.43(ISP1) U1.46(ISP3) U3.1(VIN)
ISP_DCR: C4.2 C51.1 R42.1 R42.2 R56.1 R95.2 R102.1 R105.2 TP19.1 TP25.1 U1.35(ISP)
MODE: C35.2 E6.1(TP) J5.3 J6.3 JP3.2 U1.30(MODE)
PGOOD: E17.1(TP) R16.1 U2.2(PGOOD)
PLLIN/MODE: E26.1(TP) R25.2 R62.2
REG: C3.2 D1.2(K) D2.2(K) D3.2(K) D4.2(K) Q21.2(D) Q21.4(D) R10.2 R57.1 R57.2 R58.1 R58.2 R59.1 R59.2 R60.1 R60.2 U1.3(REG)
REGSNS: E21.1(TP) J5.4 J6.4 R7.1 R49.1 TP13.1
RUN: D8.1 E13.1(TP) R9.2 R30.2
SENSE+_DCR: C30.2 R22.2 R84.2 R85.2 R102.2 TP20.1 U2.14(SENSE+)
SENSE-: L5.2 R21.1 R53.2 R85.1 RSNS5.2 TP14.1
SENSE-_DCR: C30.1 R21.2 R83.2 R84.1 R103.2 TP3.1 U2.13(SENSE-)
SHDN: E8.1(TP) JP2.2 R2.2 R3.2 U1.31(~{SHDN})
SW: C22.2 L5.1 Q17.1(SOURCE) Q17.2(SOURCE) Q17.3(SOURCE) Q18.1(SOURCE) Q18.2(SOURCE) Q18.3(SOURCE) Q19.5(DRAIN) Q20.5(DRAIN) R35.2 R83.1 TP24.1 U2.18(SW)
SYNC: E19.1(TP) JP1.1 R32.2
TG: R36.2 R99.2 TP23.1 U2.19(TG)
TGBUF: R39.1 TP6.1 U1.13(TGBUF)
TGBUF/TGSH: E11.1(TP) J5.10 J6.10 R31.1 R39.2
TGSH: R8.2 R31.2 R36.1 TP15.1
TGSL: C36.1 C56.1 D6.2(K) D7.1(A) R35.1 R63.2 TP16.1 U1.19(TGSL)
TGSR: C5.2 C36.2 R37.1 R97.1 TP7.1 U1.17(TGSR)
VAUX: C1.2 C24.1 C26.1 C32.1 R29.1 R94.1 R94.2 R98.1 R120.2 TP2.1 TP30.1 U1.49(VIN) U3.12(VOUT)
VOUT: C14.1 C37.1 C60.1 C61.1 COUT1.1 COUT2.1 COUT3.1 COUT4.1 COUT5.1 COUT6.1 COUT7.1 COUT8.1 COUT9.1 COUT10.1 COUT11.1 COUT12.1 COUT13.1 COUT14.1 COUT15.1 D6.1(A) E9.1(TP) J3.1 Q1.5(DRAIN) Q2.5(DRAIN) Q5.5(DRAIN) Q6.5(DRAIN) Q9.5(DRAIN) Q10.5(DRAIN) Q13.5(DRAIN) Q14.5(DRAIN) Q17.5(DRAIN) Q18.5(DRAIN) R19.2
N18430581: C17.2 C40.2 L1.1 Q1.1(SOURCE) Q1.2(SOURCE) Q1.3(SOURCE) Q2.1(SOURCE) Q2.2(SOURCE) Q2.3(SOURCE) Q3.5(DRAIN) Q4.5(DRAIN) R72.1 U1.16(SW1)
N18430618: C40.1 Q1.4(GATE) Q2.4(GATE) R86.1 R86.2 U1.15(TG1)
N18430651: Q3.4(GATE) Q4.4(GATE) R87.1 R87.2 U1.11(BG1)
N18430719: C17.1 D1.1(A) R67.1 R67.2 U1.14(BST1)
N18432657: C19.2 C38.2 L2.1 Q5.1(SOURCE) Q5.2(SOURCE) Q5.3(SOURCE) Q6.1(SOURCE) Q6.2(SOURCE) Q6.3(SOURCE) Q7.5(DRAIN) Q8.5(DRAIN) R73.1 U1.9(SW2)
N18432669: C38.1 Q5.4(GATE) Q6.4(GATE) R88.1 R88.2 U1.8(TG2)
N18432687: Q7.4(GATE) Q8.4(GATE) R89.1 R89.2 U1.10(BG2)
N18432781: C19.1 D2.1(A) R66.1 R66.2 U1.7(BST2)
N18462849: Q15.4(GATE) Q16.4(GATE) R90.1 R90.2 U1.1(BG4)
N18462895: C20.2 C39.2 L4.2 Q13.1(SOURCE) Q13.2(SOURCE) Q13.3(SOURCE) Q14.1(SOURCE) Q14.2(SOURCE) Q14.3(SOURCE) Q15.5(DRAIN) Q16.5(DRAIN) R75.1 U1.50(SW4)
N18462912: C39.1 Q13.4(GATE) Q14.4(GATE) R93.1 R93.2 U1.51(TG4)
N18462994: C20.1 D4.1(A) R64.1 R64.2 U1.52(BST4)
N18466721: C18.2 C41.2 L3.2 Q9.1(SOURCE) Q9.2(SOURCE) Q9.3(SOURCE) Q10.1(SOURCE) Q10.2(SOURCE) Q10.3(SOURCE) Q11.5(DRAIN) Q12.5(DRAIN) R74.1 U1.4(SW3)
N18466729: Q11.4(GATE) Q12.4(GATE) R92.1 R92.2 U1.2(BG3)
N18466751: C41.1 Q9.4(GATE) Q10.4(GATE) R91.1 R91.2 U1.5(TG3)
N18466850: C18.1 D3.1(A) R65.1 R65.2 U1.6(BST3)
N18477908: Q21.3(S) U1.47(REGIS)
N18477910: Q21.1(G) U1.48(REGDRV)
N18477928: C7.2 R43.2 R81.1 U1.27(ILIM)
N18477935: C5.1 C56.2 R8.1 U1.18(TGSH)
N18480103: C27.2 R7.2 U1.40(REGSNS)
N18510074: R118.1 R119.2 U1.41(PHS3)
N18510086: C9.2 R116.1 R117.2 U1.24(PHS2)
N18510108: C8.2 R114.1 R115.2 U1.25(PHS1)
N18510127: R1.2 R80.1 U1.26(RT/MS)
N18510138: C52.2 R23.2 U1.20(CLK2)
N18510146: C55.2 R24.2 U1.23(SYNC)
N18510154: C54.2 R5.1 U1.22(BGSH)
N18602495: C23.2 R34.1 TP1.1 U2.1(VBIAS)
N18658123: C14.2 R17.2 R18.1 U2.15(VFB)
N18658279: R18.2 R19.1
N18658287: Q17.4(GATE) Q18.4(GATE) R99.1
N18658309: Q19.4(GATE) Q20.4(GATE) R100.1
N18663418: JP1.2 R24.1
N18838508: R101.2 U2.20(BOOST)
N18948226: C21.2 U3.18(BST)
N18948246: C34.1 U3.10(TR/SS)
N18948252: C33.1 R54.2 U3.16(INTVCC)
N18948280: R26.1 R54.1 U3.7(SYNC/MODE)
N18948288: R27.2 U3.8(RT)
N18948302: C26.2 R28.1 R29.2 U3.11(FB)
N18948320: R52.1 R61.2 U3.3(EN/UV)
N18948338: C21.1 L6.2 U3.20(SW)
N18948391: L6.1 U3.14(IND)
N18965098: R50.1 R82.2 U2.7(FREQ)
N18965154: C15.1 R25.1 R51.2 U2.9(PLLIN/MODE)
N18965186: C25.1 U2.12(SS)
N18965206: C57.1 D8.2 R9.1 R55.1 U2.11(RUN)
N18965292: C58.1 R20.2 U2.16(ITH)
N19044750: R112.1 R113.2 U2.17(OVMODE)
N19045378: C31.1 R20.1
N19047556: R104.1 R111.2 U2.3(ILIM)

Not connected (* = marked no-connect by the designer): JP2 3; JP3 1; U1 42(NC); U2 4(NC)* 6(NC)*; U3 5(PG) 6(NC)* 9(NC)* 13(NC)* 15(NC)*

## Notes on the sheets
sheet 1
- [3.]
- WITH INTERNAL GATE DRIVERS
- 02-07-2018
- NOTE: UNLESS OTHERWISE SPECIFIED
- - SEE QUICK START GUIDE
- 1.  ALL RESISTORS ARE IN OHMS, 0603.
       ALL CAPACITORS ARE IN MICROFARADS, 0603.
sheet 2
- STAGE SHED
- [2.]
- [4.]
- PHS1
- GND
- [2.]
- FLOAT
- GND
- 350kHz
- REG
- PHS2
- [2.]
- [2.]
- GND
- TDPN SET
- REG
- PHS3
- [2.]
- GND
- [2.]
- [2.]
- [2.]
- REG
- [2.]
- [2.]
- [2.]
- [2.]
- [2.]
- WITH INTERNAL GATE DRIVERS
- 02-07-2018
sheet 3
- WITH INTERNAL GATE DRIVERS
- 02-07-2018
- NOTE: UNLESS OTHERWISE SPECIFIED
- 1.  ALL RESISTORS ARE IN OHMS, 0603.
       ALL CAPACITORS ARE IN MICROFARADS, 0603.
sheet 4
- WITH INTERNAL GATE DRIVERS
- 02-07-2018
sheet 5
- *
- [2.]
- *
- SEE THE DEMO MANUAL FOR CURRENT RATING
- OPT
- [2.]
- SLV CONNECT PRM
- OPT
- [2.]
- SLV CONNECT SEC
- [2.]
- OPTIONAL
  DCR SENSE
- WITH INTERNAL GATE DRIVERS
- LTC3769
- [1.]
- LT8551
- [3.]
- PRIMARY CONTROLLER
- 02-07-2018
sheet 6
- NOTES:
- 400kHz
- [1.]
- ASSY
- LT8551 MASTER / SLAVE
- OPTIONAL CIRCUIT
  TO REDUCE POWER
  DISSIPATION IN Q21
- -A
- MASTER
- -B
- SLAVE
- [2.]
- ASSY
- R1
- R4
- R6,R39,R40,R41
- R8
- R31,R32,R33,R63,
  R80,R95.R96,R97
- C5
- C36
- D6,D7
- -A
- 71.5K
- 47K
- 0 OHM
- 20
- OPT
- 1nF
- 10nF
- BAT46WJ
- -B
- OPT
- OPT
- OPT
- 0 OHM
- 0 OHM
- OPT
- OPT
- OPT
- [3.]
- [4.]
- LTC3769 PRIMARY CONTROLLER
  COMPONENTS INSTALLED / REMOVED
- ASSY
- ASSY
- JP4 (STAGE SHED)
- -A
- INSTALLED
- -A
- DISABLE
- -B
- REMOVED
- -B
- ENABLE
- [5.]
- ASSY
- JP5 (SYNC)
- -A
- GND
- -B
- SYNC
- 6.  UNLESS OTHERWISE SPECIFIED,
       ALL RESISTORS ARE 0603, 5%
       AND ALL CAPACITORS ARE 0603.
- WITH INTERNAL GATE DRIVERS
- 02-07-2018
